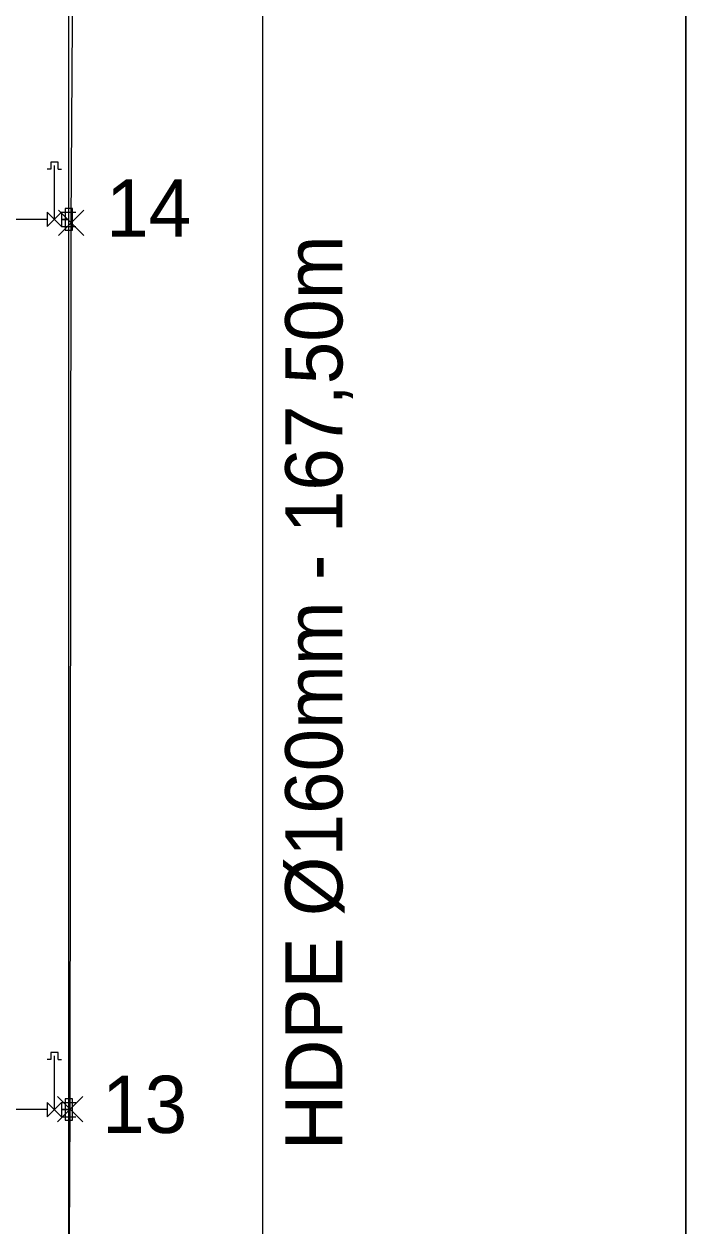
# Model space of a CAD drawing. Extents: x -263964 to -263544, y -1242317 to -1242020.
# Drawn here: x -263789.71 to -263766.58, y -1242184 to -1242142.01 of the extents above; entities that cross this region are included whole.
import ezdxf

# ---------------------------------------------------------------- set-up
doc = ezdxf.new("R2010")
doc.units = 0
for name, color, linetype in [('KFA_KOORDINACNA_SITUACIA_DSP_SEDA', 7, 'Continuous'), ('KFA_SO_50-2_POZIARNY_VODOVOD_BODY', 7, 'Continuous'), ('KFA_SO_50-2_POZIARNY_VODOVOD_TRASA', 7, 'Continuous'), ('POPIS', 7, 'Continuous')]:
    doc.layers.add(name, color=color, linetype=linetype)

msp = doc.modelspace()

# ---------------------------------------------------------------- linework, layer by layer
at = {"layer": 'KFA_KOORDINACNA_SITUACIA_DSP_SEDA'}
for p, q in [((-263766.58, -1242144.85), (-263766.58, -1242074.389)), ((-263788.143, -1242250.14), (-263788.143, -1242082.64)), ((-263766.58, -1242083.485), (-263766.58, -1242201.01)), ((-263781.364, -1242208.936), (-263781.371, -1242084.903)), ((-263766.58, -1242201.01), (-263766.58, -1242144.85)), ((-263788.768, -1242146.832), (-263788.768, -1242147.082)), ((-263788.518, -1242146.832), (-263788.768, -1242146.832)), ((-263788.518, -1242147.082), (-263788.518, -1242146.832)), ((-263788.768, -1242147.082), (-263788.893, -1242147.082)), ((-263788.643, -1242148.832), (-263788.643, -1242146.957)), ((-263788.518, -1242147.082), (-263788.393, -1242147.082)), ((-263788.268, -1242148.457), (-263788.268, -1242149.207)), ((-263788.018, -1242148.457), (-263788.268, -1242148.457)), ((-263788.018, -1242149.207), (-263788.018, -1242148.457)), ((-263788.893, -1242148.832), (-263800.593, -1242148.832)), ((-263788.893, -1242148.582), (-263788.893, -1242149.082)), ((-263788.393, -1242149.082), (-263788.893, -1242148.582)), ((-263788.893, -1242149.082), (-263788.393, -1242148.582)), ((-263788.393, -1242148.582), (-263788.393, -1242149.082)), ((-263788.393, -1242148.582), (-263787.893, -1242148.582)), ((-263788.143, -1242148.832), (-263788.393, -1242148.832)), ((-263788.393, -1242148.832), (-263788.143, -1242148.832)), ((-263788.393, -1242149.082), (-263787.893, -1242149.082)), ((-263788.268, -1242149.207), (-263788.018, -1242149.207)), ((-263788.768, -1242177.932), (-263788.768, -1242178.182)), ((-263788.518, -1242177.932), (-263788.768, -1242177.932)), ((-263788.518, -1242178.182), (-263788.518, -1242177.932)), ((-263788.768, -1242178.182), (-263788.893, -1242178.182)), ((-263788.643, -1242179.932), (-263788.643, -1242178.057)), ((-263788.518, -1242178.182), (-263788.393, -1242178.182)), ((-263788.268, -1242179.557), (-263788.268, -1242180.307)), ((-263788.018, -1242179.557), (-263788.268, -1242179.557)), ((-263788.018, -1242180.307), (-263788.018, -1242179.557)), ((-263788.893, -1242179.932), (-263800.593, -1242179.932)), ((-263788.893, -1242179.682), (-263788.893, -1242180.182)), ((-263788.393, -1242180.182), (-263788.893, -1242179.682)), ((-263788.893, -1242180.182), (-263788.393, -1242179.682)), ((-263788.393, -1242179.682), (-263788.393, -1242180.182)), ((-263788.393, -1242179.682), (-263787.893, -1242179.682)), ((-263788.143, -1242179.932), (-263788.393, -1242179.932)), ((-263788.393, -1242179.932), (-263788.143, -1242179.932)), ((-263788.393, -1242180.182), (-263787.893, -1242180.182)), ((-263788.268, -1242180.307), (-263788.018, -1242180.307))]:
    msp.add_line(p, q, dxfattribs=at)
at = {"layer": 'KFA_SO_50-2_POZIARNY_VODOVOD_BODY'}
for p, q in [((-263788.504, -1242149.4), (-263787.62, -1242148.516)), ((-263787.62, -1242149.4), (-263788.504, -1242148.516)), ((-263788.062, -1242148.958), (-263788.062, -1242148.958)), ((-263788.534, -1242180.357), (-263787.65, -1242179.473)), ((-263787.65, -1242180.357), (-263788.534, -1242179.473)), ((-263788.092, -1242179.915), (-263788.092, -1242179.915))]:
    msp.add_line(p, q, dxfattribs=at)
at = {"layer": 'KFA_SO_50-2_POZIARNY_VODOVOD_TRASA'}
msp.add_lwpolyline([(-263924.931, -1242185.127), (-263924.146, -1242197.091), (-263924.296, -1242220.899), (-263924.1, -1242250.121), (-263913.986, -1242249.798), (-263886.91, -1242249.876), (-263867.714, -1242249.83), (-263837.257, -1242249.836), (-263828.162, -1242249.901), (-263787.99, -1242250.032), (-263788.202, -1242220.837), (-263788.195, -1242200.509), (-263788.092, -1242179.915), (-263788.062, -1242148.958), (-263787.919, -1242127.952), (-263787.952, -1242110.966), (-263788.129, -1242082.536), (-263828.429, -1242082.723), (-263836.783, -1242082.559), (-263867.306, -1242082.615), (-263886.71, -1242082.472), (-263924.08, -1242082.613), (-263924.644, -1242106.322), (-263924.479, -1242117.427)], close=True, dxfattribs=at)

# ---------------------------------------------------------------- texts
at = {"layer": 'KFA_SO_50-2_POZIARNY_VODOVOD_BODY'}
for s, p in [('14', (-263786.839, -1242149.44)), ('13', (-263786.979, -1242180.749))]:
    msp.add_text(s, height=2, dxfattribs=at).set_placement(p)
at = {"layer": 'POPIS'}
msp.add_text('HDPE Ø160mm - 167,50m', height=2, rotation=90, dxfattribs=at).set_placement((-263778.582, -1242181.349))

doc.saveas('drawing.dxf')
